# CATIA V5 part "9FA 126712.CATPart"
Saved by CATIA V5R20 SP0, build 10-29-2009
Part number: 9FA 126712
Revision: ANY
Definition: UNKNOWN
Nomenclature: 9FA 126712
Source: Unknown
Bounding box of the stored display mesh (mm): x -5.85 to 5.85, y -10 to 10, z -6 to 6
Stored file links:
  C:\Users\Utente\Desktop\IO LAVORO\3D X SITO CF\CUMSA\3D files FA\FA 1267SF\9FA 126712.CATPart

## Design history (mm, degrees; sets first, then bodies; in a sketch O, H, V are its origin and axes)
Body1 "Cortar-Extruir5" (main body)
  Solid1: solid without history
